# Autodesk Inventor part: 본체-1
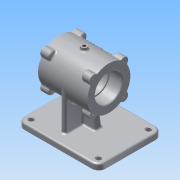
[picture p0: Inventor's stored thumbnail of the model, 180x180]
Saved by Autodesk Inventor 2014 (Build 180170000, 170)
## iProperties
Created: 2016-01
Part Number: 본체-1
Material: 알루미늄 6061
Document SubType Name: Modeling
Designer: Administrator
Density: 2.71 g/cm^3
Appearance: 알루미늄 - 평지
Mass: 1037.38 g
Surface Area: 821.121 cm^2
Volume: 382.798 cm^3
Author: Administrator
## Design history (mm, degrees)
sketch "스케치1"
  geometry: C1 r 37 at (0, 0); 1 further point
  constraints: 1 centre point, 1 coincident
  dimensions: "d0" = 74 diameter of C1
extrude "돌출1" new body sketch "스케치1" stored distance "d1" = 85; taper "d2" = 0 deg
sketch "스케치2"
  geometry: L1 (0, 0)-(26.163, 26.163); L2 (0, 0)-(37, 0); C1 r 7 at (26.163, 26.163)
  constraints: 4 end point, 1 centre point, 1 coincident, 1 equal length, 1 horizontal, 2 other
  dimensions: "d3" = 45 deg angle of L2 L1; "d4" = 14 diameter of C1
extrude "돌출2" join sketch "스케치2" distance "d5" = 15; taper "d6" = 0 deg
node "작업 평면1"
sketch "스케치3"
  geometry: L1 (55, 80)-(-55, 80); L2 (-55, 80)-(-55, -60); L3 (-55, -60)-(55, -60); L4 (55, -60)-(55, 80); L5 (20.767, 42.5)-(-20.767, 42.5) reference; 1 further point
  constraints: 8 end point, 2 parallel, 1 horizontal, 1 perpendicular
  dimensions: "d11" = 37.5 distance between parallel lines of L1 L5; "d12" = 140 distance between parallel lines of L3 L1; "d13" = 55 distance from line of point (0, 0) L4; "d14" = 110 distance between parallel lines of L2 L4
extrude "돌출3" join sketch "스케치3" distance "d15" = 10; taper "d16" = 0 deg
sketch "스케치4"
  geometry: L1 (37, 42.5)-(37, -42.5) reference; L2 (37, -42.5)-(-37, -42.5) reference; L3 (-37, -42.5)-(-37, 42.5) reference; L4 (-37, 42.5)-(37, 42.5) reference; L5 (-80, 80)-(-70, 80) reference; L6 (-70, 80)-(-70, -60) reference; L7 (-70, -60)-(-80, -60) reference; L8 (-80, -60)-(-80, 80) reference; L9 (-70, 25)-(-19.194, 16.953); L10 (-70, 0)-(0, 0); L11 (-70, -25)-(-19.194, -16.953); L12 (-19.194, 16.953)-(-19.194, -16.953); L13 (-70, -25)-(-70, 25)
  constraints: 10 end point, 2 perpendicular, 2 point on line, 2 symmetric about line, 1 collinear
  dimensions: "d17" = 25 distance of L9.start L10.start; "d18" = 99 deg angle of L6 L9; "d19" = 56.19381 distance between parallel lines of L1 L12
extrude "돌출4" join sketch "스케치4" stored distance "d20" = 12; taper "d21" = 0 deg
sketch "스케치5"
  geometry: L1 (55, -70)-(55, -80) reference; L2 (55, -80)-(-55, -80) reference; L3 (-55, -80)-(-55, -70) reference; L4 (-55, -70)-(-6, -70) reference; L5 (-6, -70)-(-6, -36.51) reference; L6 (6, -36.51)-(6, -70) reference; L7 (6, -70)-(55, -70) reference; L8 (-37, 0)-(37, 0); L9 (37, 0)-(37, -70); L10 (37, -70)-(-37, -70); L11 (-37, -70)-(-37, 0); A1 r 37 centre (0, 0) between (6, -36.51) and (-6, -36.51) reference; 2 further points
  constraints: 8 end point, 2 parallel, 2 tangent, 1 coincident, 1 horizontal, 1 midpoint, 1 perpendicular, 1 point on line
extrude "돌출5" join sketch "스케치5" stored distance "d22" = 8; taper "d23" = 0 deg
fillet "모깎기1" dims "d24" = 12
sketch "스케치7"
  geometry: C1 r 4 at (-43, 48); C2 r 4 at (43, 48); C3 r 4 at (43, -68); C4 r 4 at (-43, -68); A1 r 12 centre (-43, -68) between (-55, -68) and (-43, -80) reference; A2 r 12 centre (43, -68) between (43, -80) and (55, -68) reference; A3 r 12 centre (43, 48) between (55, 48) and (43, 60) reference; A4 r 12 centre (-43, 48) between (-43, 60) and (-55, 48) reference; 1 further point
  constraints: 4 centre point, 4 coincident
  dimensions: "d25" = 8 diameter of C1; "d26" = 8 diameter of C2; "d27" = 8 diameter of C3; "d28" = 8 diameter of C4
extrude "돌출6" cut sketch "스케치7" distance "d29" = 15; taper "d30" = 0 deg
sketch "스케치8"
  geometry: L1 (55, 68)-(55, -48) reference; L2 (-43, 80)-(43, 80) reference; L3 (55, 68)-(55, -48) reference; L4 (43, -60)-(-43, -60) reference; L5 (-55, -48)-(-55, 68) reference; L6 (23.226, 65)-(-23.226, 65); L7 (-40, 48.226)-(-40, -28.226); L8 (-23.226, -45)-(23.226, -45); L9 (40, -28.226)-(40, 48.226); C1 r 4 at (43, 68) reference; C2 r 4 at (-43, -48) reference; C3 r 4 at (43, -48) reference; C4 r 4 at (-43, 68) reference; A1 r 20 centre (43, 68) between (23.226, 65) and (40, 48.226); A2 r 12 centre (-43, 68) between (-43, 80) and (-55, 68) reference; A3 r 12 centre (43, 68) between (55, 68) and (43, 80) reference; A4 r 12 centre (43, -48) between (43, -60) and (55, -48) reference; A5 r 12 centre (-43, -48) between (-55, -48) and (-43, -60) reference; A6 r 20 centre (-43, -48) between (-23.226, -45) and (-40, -28.226); A7 r 20 centre (-43, 68) between (-40, 48.226) and (-23.226, 65); A8 r 20 centre (43, -48) between (40, -28.226) and (23.226, -45); 1 further point
  constraints: 8 end point, 8 point on circle, 4 centre point, 4 coincident, 2 parallel, 1 horizontal, 1 perpendicular
  dimensions: "d33" = 40 diameter of A1; "d35" = 40 diameter of A6; "d36" = 40 diameter of A7; "d37" = 40 diameter of A8; "d38" = 15 distance between parallel lines of L1 L9; "d39" = 15 distance between parallel lines of L2 L6; "d40" = 15 distance between parallel lines of L5 L7; "d41" = 15 distance between parallel lines of L4 L8
extrude "돌출7" cut sketch "스케치8" distance "d42" = 5; taper "d43" = 0 deg
hole "구멍1" diameter "d46" = 47; stored, may be unused: countersink angle "d50" = 90 deg, drill point angle "d52" = 0 deg; dims "d44" = 10, "d45" = 10, "d47" = 6, "d48" = 4, "d49" = 2, "d51" = 22
hole "구멍2" diameter "d55" = 42; stored, may be unused: countersink angle "d59" = 90 deg, drill point angle "d61" = 0 deg; dims "d53" = 10, "d54" = 10, "d56" = 6, "d57" = 4, "d58" = 2, "d60" = 41
hole "구멍3" diameter "d64" = 47; stored, may be unused: countersink angle "d68" = 90 deg, drill point angle "d70" = 0 deg; dims "d62" = 10, "d63" = 10, "d65" = 6, "d66" = 4, "d67" = 2, "d69" = 22
node "작업 평면2"
sketch "스케치9"
  geometry: C1 r 5 at (0, 0); 1 further point
  constraints: 1 centre point, 1 coincident
  dimensions: "d72" = 10 diameter of C1
extrude "돌출8" join sketch "스케치9" stored distance "d73" = 5; taper "d74" = 0 deg
hole "구멍4" diameter "d77" = 5.188; stored, may be unused: countersink angle "d81" = 90 deg, drill point angle "d83" = 0 deg; dims "d78" = 100, "d79" = 4, "d80" = 2, "d82" = 150, "d84" = 10, "d85" = 10
fillet "모깎기2" dims "d86" = 0.3
fillet "모깎기3" dims "d87" = 3
fillet "모깎기4" dims "d88" = 1
sketch "스케치12"
  geometry: A1 r 7 centre (26.163, 26.163) between (30.622, 20.767) and (20.767, 30.622) reference; 1 further point
  constraints: 1 coincident
hole "구멍5" sketch "스케치12" at (26.163, 26.163) diameter "d89" = 3.242; stored, may be unused: countersink angle "d93" = 90 deg, drill point angle "d95" = 118 deg; dims "d90" = 9, "d91" = 4, "d92" = 2, "d94" = 11
chamfer "모따기1" distance "d99" = 1; stored, may be unused: second distance "d100" = 2, angle "d101" = 45 deg
fillet "모깎기5" dims "d102" = 4
fillet "모깎기6" dims "d103" = 3
fillet "모깎기7" dims "d104" = 3
fillet "모깎기8" dims "d105" = 3
fillet "모깎기9" dims "d106" = 3
fillet "모깎기10" dims "d107" = 3
fillet "모깎기11" dims "d108" = 3
fillet "모깎기12" dims "d109" = 3
fillet "모깎기13" dims "d110" = 3
fillet "모깎기14" dims "d111" = 3
fillet "모깎기15" dims "d112" = 3
fillet "모깎기16" dims "d113" = 3
sketch "스케치13"
  geometry: L1 (0, 0)-(41.197, 41.197); L2 (0, 0)-(58.261, 0); C1 r 1.621 at (26.163, 26.163) reference; C2 r 1.621 at (-26.163, 26.163) reference; C3 r 1.621 at (-26.163, -26.163) reference; C4 r 1.621 at (26.163, -26.163) reference; C5 r 24.5 at (0, 0) reference; A1 r 37 centre (0, 0) between (31.796, -18.921) and (31.796, 18.921) reference; A2 r 3 centre (34.374, 20.455) between (31.911, 22.168) and (31.796, 18.921) reference; A3 r 7 centre (26.163, 26.163) between (31.911, 22.168) and (22.168, 31.911) reference; A4 r 3 centre (20.455, 34.374) between (18.921, 31.796) and (22.168, 31.911) reference; A5 r 37 centre (0, 0) between (18.921, 31.796) and (-18.921, 31.796) reference; A6 r 3 centre (-20.455, 34.374) between (-22.168, 31.911) and (-18.921, 31.796) reference; A7 r 7 centre (-26.163, 26.163) between (-22.168, 31.911) and (-31.911, 22.168) reference; A8 r 3 centre (-34.374, 20.455) between (-31.796, 18.921) and (-31.911, 22.168) reference; A9 r 37 centre (0, 0) between (-31.796, 18.921) and (-31.796, -18.921) reference; A10 r 3 centre (-34.374, -20.455) between (-31.911, -22.168) and (-31.796, -18.921) reference; A11 r 7 centre (-26.163, -26.163) between (-31.911, -22.168) and (-22.168, -31.911) reference; A12 r 3 centre (-20.455, -34.374) between (-18.921, -31.796) and (-22.168, -31.911) reference; A13 r 37 centre (0, 0) between (-18.921, -31.796) and (18.921, -31.796) reference; A14 r 3 centre (20.455, -34.374) between (22.168, -31.911) and (18.921, -31.796) reference; A15 r 7 centre (26.163, -26.163) between (22.168, -31.911) and (31.911, -22.168) reference; A16 r 3 centre (34.374, -20.455) between (31.796, -18.921) and (31.911, -22.168) reference
  constraints: 4 end point, 1 equal length, 1 horizontal
  dimensions: "d114" = 45 deg angle of L2 L1
node "작업 평면3"
sketch "스케치14"
  geometry: L1 (35.862, 0)-(9.104, 0) reference; 2 further points
  constraints: 1 coincident, 1 other
  dimensions: "d115" = 42.5 distance from line of point (0, -42.5) L1
feature "엠보싱1" sketch "스케치14" dims "d116" = 0.5, "d117" = 0
node "솔리드1"
pattern_circular "원형 패턴1" dims angle "d8" = 360 deg
mirror "대칭1"
pattern_circular "원형 패턴2" dims angle "d97" = 360 deg
mirror "대칭2"
node "절단 모서리 투영1"
node "절단 모서리 투영2"
node "절단 모서리 투영3"
other parameters: "d71" = -122
